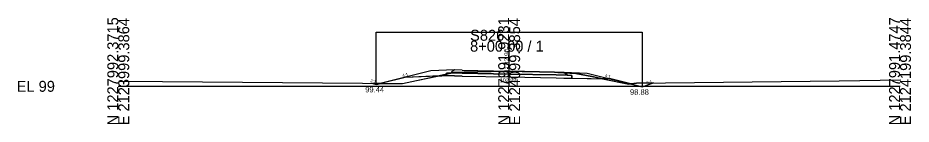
# Model space of a CAD drawing. Extents: x 2118382 to 2118616, y 1213030 to 1222057.
# Drawn here: x 2118381.9 to 2118610.4, y 1218530.1 to 1218557.3 of the extents above; entities that cross this region are included whole.
import ezdxf

# ---------------------------------------------------------------- set-up
doc = ezdxf.new("R2010")
doc.units = 0
for name, color, linetype in [('XS_CELL', 7, 'Continuous'), ('XS_M_DITCH', 7, 'Continuous'), ('XS_M_SHAPES_EARTHWORK', 7, 'Continuous'), ('XS_P_FINISHED_GRADE', 7, 'Continuous'), ('XS_P_FINISHED_GRADE_ELEV_TX', 7, 'Continuous'), ('XS_P_SUBGRADE_GRANULAR', 7, 'Continuous'), ('XS_P_SUBGRADE_PAVEMENT', 7, 'Continuous'), ('XS_P_TX_DCH', 7, 'Continuous'), ('XS_P_TX_FS_BS', 7, 'Continuous'), ('XS_X_GROUND', 7, 'Continuous'), ('XS_X_GROUND_TX', 7, 'Continuous')]:
    doc.layers.add(name, color=color, linetype=linetype)

msp = doc.modelspace()

# ---------------------------------------------------------------- linework, layer by layer
at = {"layer": 'XS_CELL'}
for p, q in [((2118507.6, 1218539.8), (2118507.6, 1218551.47)), ((2118407.6, 1218539.8), (2118507.6, 1218539.8)), ((2118507.6, 1218539.8), (2118607.6, 1218539.8))]:
    msp.add_line(p, q, dxfattribs=at)
at = {"layer": 'XS_M_DITCH'}
for p, q in [((2118473.6, 1218540.24), (2118473.6, 1218553.7)), ((2118473.6, 1218553.7), (2118541.6, 1218553.7)), ((2118541.6, 1218553.7), (2118541.6, 1218539.68))]:
    msp.add_line(p, q, dxfattribs=at)
at = {"layer": 'XS_M_SHAPES_EARTHWORK'}
for p, q in [((2118491.6, 1218542.94), (2118489.25, 1218542.43)), ((2118493.04, 1218543.25), (2118491.6, 1218542.94)), ((2118491.6, 1218542.53), (2118491.6, 1218542.94)), ((2118491.6, 1218542.94), (2118491.6, 1218542.53)), ((2118493.42, 1218543.33), (2118493.04, 1218543.25)), ((2118495.6, 1218543.19), (2118493.04, 1218543.25)), ((2118493.04, 1218543.25), (2118495.6, 1218543.19)), ((2118494.21, 1218543.36), (2118493.42, 1218543.33)), ((2118496.1, 1218543.41), (2118494.21, 1218543.36)), ((2118507.6, 1218542.95), (2118495.6, 1218543.19)), ((2118495.6, 1218543.19), (2118507.6, 1218542.95)), ((2118506.4, 1218543.66), (2118496.1, 1218543.41)), ((2118507.6, 1218543.68), (2118506.4, 1218543.66)), ((2118510.91, 1218543.61), (2118507.6, 1218543.68)), ((2118519.6, 1218542.71), (2118507.6, 1218542.95)), ((2118507.6, 1218542.95), (2118519.6, 1218542.71)), ((2118511.53, 1218543.59), (2118510.91, 1218543.61)), ((2118519.19, 1218543.4), (2118511.53, 1218543.59)), ((2118520.06, 1218543.34), (2118519.19, 1218543.4)), ((2118522.45, 1218542.65), (2118519.6, 1218542.71)), ((2118519.6, 1218542.71), (2118522.45, 1218542.65)), ((2118521.85, 1218543.25), (2118520.06, 1218543.34)), ((2118522.28, 1218542.95), (2118521.85, 1218543.25)), ((2118524.64, 1218543.11), (2118521.85, 1218543.25)), ((2118521.85, 1218543.25), (2118522.28, 1218542.95)), ((2118522.45, 1218542.65), (2118522.28, 1218542.95)), ((2118522.28, 1218542.95), (2118522.45, 1218542.65)), ((2118528.78, 1218542.28), (2118524.64, 1218543.11)), ((2118472.7, 1218540.55), (2118473.6, 1218540.24)), ((2118474.74, 1218540.53), (2118472.7, 1218540.55)), ((2118473.6, 1218540.24), (2118474.74, 1218540.53)), ((2118481.03, 1218542.1), (2118474.74, 1218540.53)), ((2118474.74, 1218540.53), (2118480.29, 1218540.48)), ((2118480.29, 1218540.48), (2118483.89, 1218541.28)), ((2118489.25, 1218542.43), (2118481.03, 1218542.1)), ((2118483.89, 1218541.28), (2118489.25, 1218542.43)), ((2118489.25, 1218542.43), (2118491.6, 1218542.53)), ((2118491.6, 1218542.53), (2118493.6, 1218542.48)), ((2118493.6, 1218542.48), (2118495.6, 1218542.44)), ((2118495.6, 1218542.44), (2118507.6, 1218542.2)), ((2118507.6, 1218542.2), (2118519.6, 1218541.96)), ((2118519.6, 1218541.96), (2118521.6, 1218541.92)), ((2118521.6, 1218541.92), (2118523.6, 1218541.88)), ((2118523.6, 1218542.61), (2118522.45, 1218542.65)), ((2118522.45, 1218542.65), (2118523.6, 1218542.61)), ((2118523.6, 1218541.88), (2118523.6, 1218542.61)), ((2118523.6, 1218542.61), (2118523.6, 1218541.88)), ((2118523.6, 1218541.88), (2118531.48, 1218541.72)), ((2118531.48, 1218541.72), (2118528.78, 1218542.28)), ((2118533.61, 1218541.68), (2118531.48, 1218541.72)), ((2118531.48, 1218541.72), (2118538.2, 1218540.32)), ((2118538.73, 1218540.4), (2118533.61, 1218541.68)), ((2118538.2, 1218540.32), (2118538.73, 1218540.4)), ((2118540.19, 1218540.62), (2118538.73, 1218540.4)), ((2118538.73, 1218540.4), (2118541.6, 1218539.68)), ((2118544.57, 1218540.67), (2118540.19, 1218540.62)), ((2118541.6, 1218539.68), (2118544.57, 1218540.67))]:
    msp.add_line(p, q, dxfattribs=at)
at = {"layer": 'XS_P_FINISHED_GRADE'}
for p, q in [((2118487.6, 1218543.74), (2118473.6, 1218540.24)), ((2118493.6, 1218543.98), (2118487.6, 1218543.74)), ((2118495.6, 1218543.94), (2118493.6, 1218543.98)), ((2118495.6, 1218543.94), (2118507.6, 1218543.7)), ((2118507.6, 1218543.7), (2118519.6, 1218543.46)), ((2118519.6, 1218543.46), (2118521.6, 1218543.42)), ((2118521.6, 1218543.42), (2118527.6, 1218543.18)), ((2118527.6, 1218543.18), (2118541.6, 1218539.68)), ((2118473.6, 1218540.24), (2118472.7, 1218540.55)), ((2118541.6, 1218539.68), (2118544.57, 1218540.67))]:
    msp.add_line(p, q, dxfattribs=at)
at = {"layer": 'XS_P_SUBGRADE_GRANULAR'}
for p, q in [((2118492.74, 1218543.25), (2118491.6, 1218543.21)), ((2118491.6, 1218542.53), (2118491.6, 1218543.21)), ((2118491.6, 1218542.53), (2118481.03, 1218542.1)), ((2118493.6, 1218542.48), (2118491.6, 1218542.53)), ((2118495.6, 1218542.44), (2118493.6, 1218542.48)), ((2118495.6, 1218542.44), (2118507.6, 1218542.2)), ((2118507.6, 1218542.2), (2118519.6, 1218541.96)), ((2118519.6, 1218541.96), (2118521.6, 1218541.92)), ((2118521.6, 1218541.92), (2118523.6, 1218541.88)), ((2118522.45, 1218542.65), (2118523.6, 1218542.61)), ((2118523.6, 1218541.88), (2118523.6, 1218542.61)), ((2118523.6, 1218541.88), (2118533.61, 1218541.68))]:
    msp.add_line(p, q, dxfattribs=at)
at = {"layer": 'XS_P_SUBGRADE_PAVEMENT'}
for p, q in [((2118492.91, 1218543.54), (2118492.74, 1218543.25)), ((2118495.6, 1218543.19), (2118492.74, 1218543.25)), ((2118493.6, 1218543.98), (2118492.91, 1218543.54)), ((2118495.6, 1218543.19), (2118507.6, 1218542.95)), ((2118507.6, 1218542.95), (2118519.6, 1218542.71)), ((2118519.6, 1218542.71), (2118522.45, 1218542.65)), ((2118521.6, 1218543.42), (2118522.28, 1218542.95)), ((2118522.28, 1218542.95), (2118522.45, 1218542.65))]:
    msp.add_line(p, q, dxfattribs=at)
at = {"layer": 'XS_X_GROUND'}
for p, q in [((2118483.89, 1218541.28), (2118493.42, 1218543.33)), ((2118493.42, 1218543.33), (2118494.21, 1218543.36)), ((2118494.21, 1218543.36), (2118496.1, 1218543.41)), ((2118496.1, 1218543.41), (2118506.4, 1218543.66)), ((2118506.4, 1218543.66), (2118507.6, 1218543.68)), ((2118507.6, 1218543.68), (2118510.91, 1218543.61)), ((2118510.91, 1218543.61), (2118511.53, 1218543.59)), ((2118511.53, 1218543.59), (2118519.19, 1218543.4)), ((2118519.19, 1218543.4), (2118520.06, 1218543.34)), ((2118520.06, 1218543.34), (2118524.64, 1218543.11)), ((2118524.64, 1218543.11), (2118528.78, 1218542.28)), ((2118407.77, 1218541.13), (2118418.92, 1218541.03)), ((2118418.92, 1218541.03), (2118480.29, 1218540.48)), ((2118480.29, 1218540.48), (2118483.89, 1218541.28)), ((2118528.78, 1218542.28), (2118538.2, 1218540.32)), ((2118538.2, 1218540.32), (2118540.19, 1218540.62)), ((2118540.19, 1218540.62), (2118592.07, 1218541.23)), ((2118592.07, 1218541.23), (2118607.77, 1218541.5))]:
    msp.add_line(p, q, dxfattribs=at)

# ---------------------------------------------------------------- texts
at = {"layer": 'XS_CELL'}
for s, p in [('N 1227992.3715', (2118407.6, 1218529.8)), ('E 2123999.3864', (2118410.4, 1218529.8)), ('N 1227991.9231', (2118507.6, 1218529.8)), ('E 2124099.3854', (2118510.4, 1218529.8)), ('N 1227991.4747', (2118607.6, 1218529.8)), ('E 2124199.3844', (2118610.4, 1218529.8))]:
    msp.add_text(s, height=2.8, rotation=90, dxfattribs=at).set_placement(p)
for s, p in [('S826', (2118497.6, 1218551.47)), ('8+00.00 / 1', (2118497.6, 1218548.67)), ('EL 99', (2118381.6, 1218538.4))]:
    msp.add_text(s, height=2.8, dxfattribs=at).set_placement(p)
at = {"layer": 'XS_P_FINISHED_GRADE_ELEV_TX'}
msp.add_text(' 102.90', height=1.25, rotation=90, dxfattribs=at).set_placement((2118507.6, 1218543.71))
at = {"layer": 'XS_P_TX_DCH'}
for s, p in [('99.44', (2118470.77, 1218538.25)), ('98.88', (2118538.51, 1218537.64))]:
    msp.add_text(s, height=1.4, dxfattribs=at).set_placement(p)
at = {"layer": 'XS_P_TX_FS_BS'}
for s, rotation, p in [('4:1', 14.0362, (2118480.36, 1218542.12)), ('4:1', 345.9638, (2118532.01, 1218542.22)), ('3:1', 341.5651, (2118471.95, 1218540.95)), ('3:1', 18.4349, (2118542.83, 1218540.18))]:
    msp.add_text(s, height=0.8, rotation=rotation, dxfattribs=at).set_placement(p)
at = {"layer": 'XS_X_GROUND_TX'}
msp.add_text('102.88', height=1, dxfattribs=at).set_placement((2118505.2, 1218540.85))

doc.saveas('drawing.dxf')
